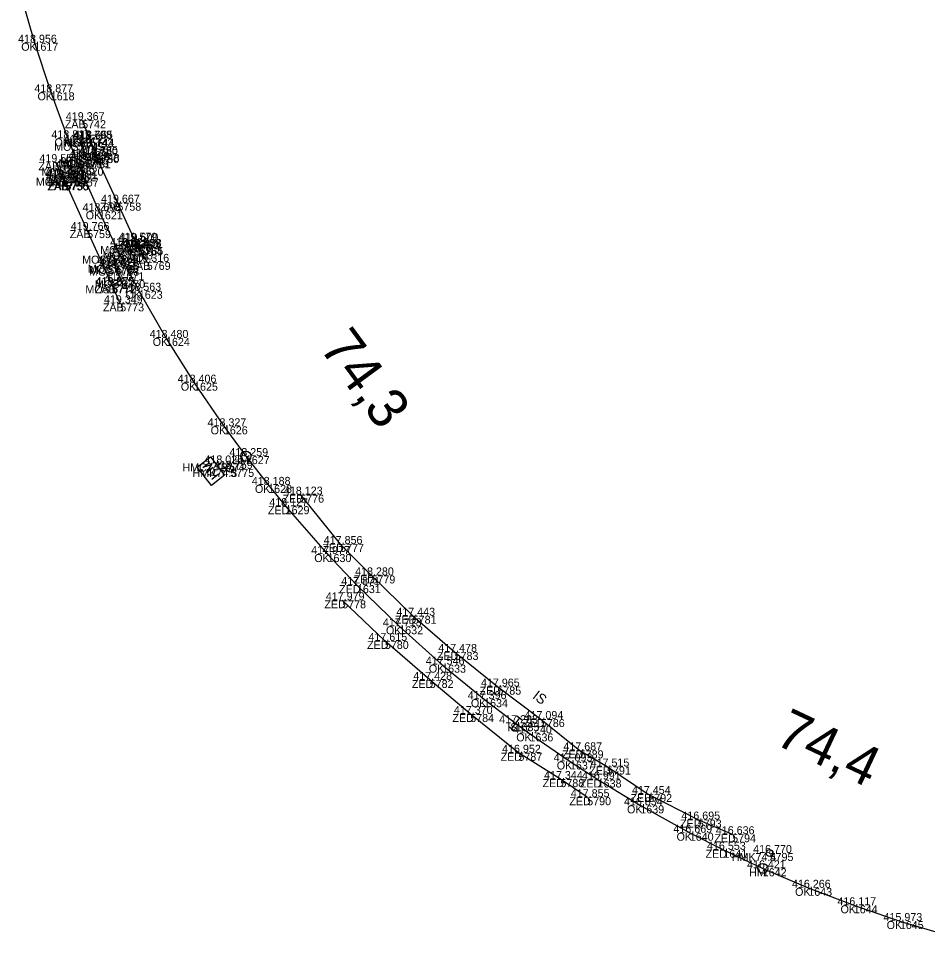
# Model space of a CAD drawing. Extents: x -621782 to -610392, y -1141853 to -1122321.
# Drawn here: x -619452.2 to -619315.9, y -1130073.6 to -1129936.1 of the extents above; entities that cross this region are included whole.
import ezdxf

# ---------------------------------------------------------------- set-up
doc = ezdxf.new("R2010")
doc.units = 0
for name, color, linetype in [('Vrstva 1', 7, 'Continuous'), ('Vrstva 13', 7, 'Continuous'), ('Vrstva 17', 7, 'Continuous'), ('Vrstva 18', 7, 'Continuous'), ('Vrstva 3', 7, 'Continuous'), ('Vrstva 60', 7, 'Continuous'), ('Vrstva 61', 7, 'Continuous'), ('Vrstva 62', 7, 'Continuous'), ('Vrstva 7', 7, 'Continuous')]:
    doc.layers.add(name, color=color, linetype=linetype)

msp = doc.modelspace()

# ---------------------------------------------------------------- linework, layer by layer
at = {"layer": 'Vrstva 1'}
msp.add_lwpolyline([(-619451.85, -1129932.46), (-619449.77, -1129939.77), (-619447.33, -1129947.2), (-619444.78, -1129954.1), (-619443, -1129958.49), (-619440.11, -1129965.04), (-619436.88, -1129971.69), (-619434.13, -1129976.95), (-619430.06, -1129984.02), (-619425.85, -1129990.73), (-619421.38, -1129997.27), (-619418.1, -1130001.74), (-619414.75, -1130006.05), (-619412.13, -1130009.24), (-619405.85, -1130016.42), (-619401.45, -1130021.07), (-619395.11, -1130027.25), (-619388.68, -1130033), (-619382.39, -1130038.17), (-619377.68, -1130041.77), (-619375.59, -1130043.3), (-619369.52, -1130047.51), (-619365.37, -1130050.21), (-619358.98, -1130054.09), (-619351.57, -1130058.19), (-619346.53, -1130060.75), (-619340.64, -1130063.53), (-619333.81, -1130066.45), (-619327, -1130069.07), (-619320.09, -1130071.43), (-619312.85, -1130073.62)], dxfattribs=at)
at = {"layer": 'Vrstva 13'}
for points in [[(-619409.94, -1130007.51), (-619403.96, -1130014.91), (-619399.27, -1130019.62), (-619393.09, -1130025.67), (-619386.81, -1130031.09), (-619380.4, -1130036.29), (-619373.88, -1130041.15), (-619368.06, -1130045.84), (-619363.97, -1130048.27), (-619357.79, -1130052.39), (-619350.37, -1130056.22), (-619345.22, -1130058.42)], [(-619366.94, -1130052.87), (-619370.96, -1130050.15), (-619377.25, -1130046.21), (-619384.47, -1130040.39), (-619390.54, -1130035.28), (-619397.26, -1130029.44), (-619403.66, -1130023.35)]]:
    msp.add_lwpolyline(points, dxfattribs=at)
at = {"layer": 'Vrstva 17'}
for points in [[(-619442.62, -1129951.38), (-619441.51, -1129954.17), (-619440.59, -1129956.43), (-619440.64, -1129956.61), (-619437.34, -1129963.75), (-619434.72, -1129969.46), (-619434.56, -1129969.53), (-619434.15, -1129970.44), (-619432.94, -1129972.62)], [(-619436.91, -1129978.84), (-619438.12, -1129976.11), (-619441.88, -1129967.85), (-619445.13, -1129960.66), (-619445.25, -1129960.71), (-619445.56, -1129959.96), (-619446.58, -1129957.68)]]:
    msp.add_lwpolyline(points, dxfattribs=at)
at = {"layer": 'Vrstva 18'}
for points in [[(-619445.62, -1129960.01), (-619444.09, -1129959.33), (-619443.72, -1129960.12), (-619441.91, -1129957.39), (-619442.22, -1129957.23), (-619441.98, -1129956.86), (-619442.88, -1129954.77), (-619441.38, -1129954.14)], [(-619438.2, -1129976.14), (-619436.76, -1129975.37), (-619437.65, -1129973.49), (-619437.52, -1129973.22), (-619437.82, -1129973.06), (-619435.98, -1129970.24), (-619435.59, -1129971.06), (-619434.05, -1129970.39)]]:
    msp.add_lwpolyline(points, dxfattribs=at)
at = {"layer": 'Vrstva 3'}
for p, q in [((-619377.07, -1130040.98), (-619378.28, -1130042.57)), ((-619377.47, -1130040.68), (-619376.67, -1130041.28)), ((-619378.68, -1130042.26), (-619377.89, -1130042.87))]:
    msp.add_line(p, q, dxfattribs=at)
at = {"layer": 'Vrstva 60'}
for p, q in [((-619449.77, -1129939.77), (-619449.77, -1129939.77)), ((-619447.33, -1129947.2), (-619447.33, -1129947.2)), ((-619442.62, -1129951.38), (-619442.62, -1129951.38)), ((-619444.78, -1129954.1), (-619444.78, -1129954.1)), ((-619442.88, -1129954.77), (-619442.88, -1129954.77)), ((-619441.51, -1129954.17), (-619441.51, -1129954.17)), ((-619441.38, -1129954.14), (-619441.38, -1129954.14)), ((-619442.22, -1129957.23), (-619442.22, -1129957.23)), ((-619441.98, -1129956.86), (-619441.98, -1129956.86)), ((-619441.91, -1129957.39), (-619441.91, -1129957.39)), ((-619440.64, -1129956.61), (-619440.64, -1129956.61)), ((-619440.59, -1129956.43), (-619440.59, -1129956.43)), ((-619446.58, -1129957.68), (-619446.58, -1129957.68)), ((-619443, -1129958.49), (-619443, -1129958.49)), ((-619445.62, -1129960.01), (-619445.62, -1129960.01)), ((-619445.56, -1129959.96), (-619445.56, -1129959.96)), ((-619444.09, -1129959.33), (-619444.09, -1129959.33)), ((-619443.72, -1129960.12), (-619443.72, -1129960.12)), ((-619445.25, -1129960.71), (-619445.25, -1129960.71)), ((-619445.13, -1129960.66), (-619445.13, -1129960.66)), ((-619437.34, -1129963.75), (-619437.34, -1129963.75)), ((-619440.11, -1129965.04), (-619440.11, -1129965.04)), ((-619441.88, -1129967.85), (-619441.88, -1129967.85)), ((-619434.72, -1129969.46), (-619434.72, -1129969.46)), ((-619434.56, -1129969.53), (-619434.56, -1129969.53)), ((-619435.98, -1129970.24), (-619435.98, -1129970.24)), ((-619435.59, -1129971.06), (-619435.59, -1129971.06)), ((-619434.15, -1129970.44), (-619434.15, -1129970.44)), ((-619434.05, -1129970.39), (-619434.05, -1129970.39)), ((-619436.88, -1129971.69), (-619436.88, -1129971.69)), ((-619432.94, -1129972.62), (-619432.94, -1129972.62)), ((-619437.82, -1129973.06), (-619437.82, -1129973.06)), ((-619437.65, -1129973.49), (-619437.65, -1129973.49)), ((-619437.52, -1129973.22), (-619437.52, -1129973.22)), ((-619436.76, -1129975.37), (-619436.76, -1129975.37)), ((-619438.2, -1129976.14), (-619438.2, -1129976.14)), ((-619438.12, -1129976.11), (-619438.12, -1129976.11)), ((-619434.13, -1129976.95), (-619434.13, -1129976.95)), ((-619436.91, -1129978.84), (-619436.91, -1129978.84)), ((-619430.06, -1129984.02), (-619430.06, -1129984.02)), ((-619425.85, -1129990.73), (-619425.85, -1129990.73)), ((-619421.38, -1129997.27), (-619421.38, -1129997.27)), ((-619421.85, -1130002.84), (-619421.85, -1130002.84)), ((-619418.1, -1130001.74), (-619418.1, -1130001.74)), ((-619420.42, -1130003.65), (-619420.42, -1130003.65)), ((-619414.75, -1130006.05), (-619414.75, -1130006.05)), ((-619409.94, -1130007.51), (-619409.94, -1130007.51)), ((-619412.13, -1130009.24), (-619412.13, -1130009.24)), ((-619403.96, -1130014.91), (-619403.96, -1130014.91)), ((-619405.85, -1130016.42), (-619405.85, -1130016.42)), ((-619399.27, -1130019.62), (-619399.27, -1130019.62)), ((-619401.45, -1130021.07), (-619401.45, -1130021.07)), ((-619403.66, -1130023.35), (-619403.66, -1130023.35)), ((-619393.09, -1130025.67), (-619393.09, -1130025.67)), ((-619395.11, -1130027.25), (-619395.11, -1130027.25)), ((-619397.26, -1130029.44), (-619397.26, -1130029.44)), ((-619386.81, -1130031.09), (-619386.81, -1130031.09)), ((-619388.68, -1130033), (-619388.68, -1130033)), ((-619390.54, -1130035.28), (-619390.54, -1130035.28)), ((-619380.4, -1130036.29), (-619380.4, -1130036.29)), ((-619382.39, -1130038.17), (-619382.39, -1130038.17)), ((-619384.47, -1130040.39), (-619384.47, -1130040.39)), ((-619373.88, -1130041.15), (-619373.88, -1130041.15)), ((-619377.68, -1130041.77), (-619377.68, -1130041.77)), ((-619375.59, -1130043.3), (-619375.59, -1130043.3)), ((-619377.25, -1130046.21), (-619377.25, -1130046.21)), ((-619368.06, -1130045.84), (-619368.06, -1130045.84)), ((-619369.52, -1130047.51), (-619369.52, -1130047.51)), ((-619363.97, -1130048.27), (-619363.97, -1130048.27)), ((-619370.96, -1130050.15), (-619370.96, -1130050.15)), ((-619365.37, -1130050.21), (-619365.37, -1130050.21)), ((-619357.79, -1130052.39), (-619357.79, -1130052.39)), ((-619366.94, -1130052.87), (-619366.94, -1130052.87)), ((-619358.98, -1130054.09), (-619358.98, -1130054.09)), ((-619350.37, -1130056.22), (-619350.37, -1130056.22)), ((-619351.57, -1130058.19), (-619351.57, -1130058.19)), ((-619345.22, -1130058.42), (-619345.22, -1130058.42)), ((-619346.53, -1130060.75), (-619346.53, -1130060.75)), ((-619339.61, -1130061.23), (-619339.61, -1130061.23)), ((-619340.64, -1130063.53), (-619340.64, -1130063.53)), ((-619333.81, -1130066.45), (-619333.81, -1130066.45)), ((-619327, -1130069.07), (-619327, -1130069.07)), ((-619320.09, -1130071.43), (-619320.09, -1130071.43))]:
    msp.add_line(p, q, dxfattribs=at)
at = {"layer": 'Vrstva 7'}
for p, q in [((-619421.85, -1130002.84), (-619422.34, -1130003.22)), ((-619422.95, -1130004.61), (-619422.71, -1130003.75)), ((-619420.45, -1130003.61), (-619420.39, -1130003.69)), ((-619423.7, -1130004.51), (-619422.53, -1130004.66)), ((-619423.19, -1130005.17), (-619422.2, -1130004.41)), ((-619339.66, -1130061.21), (-619339.57, -1130061.25))]:
    msp.add_line(p, q, dxfattribs=at)
msp.add_lwpolyline([(-619421.27, -1130004.6), (-619423.23, -1130006.12), (-619425.37, -1130003.37), (-619423.41, -1130001.85)], close=True, dxfattribs=at)
msp.add_lwpolyline([(-619422.97, -1130003.42), (-619423.95, -1130004.19), (-619423.26, -1130003.04), (-619424.54, -1130003.44), (-619423.55, -1130002.67)], dxfattribs=at)
for centre, radius in [((-619418.1, -1130001.74), 0.75), ((-619420.42, -1130003.65), 0.5), ((-619339.61, -1130061.23), 0.5), ((-619340.64, -1130063.53), 0.75)]:
    msp.add_circle(centre, radius, dxfattribs=at)

# ---------------------------------------------------------------- texts
at = {"layer": 'Vrstva 3'}
msp.add_text('IS', height=1.5, rotation=322.591, dxfattribs=at).set_placement((-619375.24, -1130037.94))
at = {"layer": 'Vrstva 60'}
for s, p in [('1617', (-619449.77, -1129940.97)), ('1618', (-619447.33, -1129948.4)), ('5742', (-619442.62, -1129952.58)), ('1619', (-619444.78, -1129955.3)), ('5745', (-619442.88, -1129955.97)), ('5743', (-619441.51, -1129955.37)), ('5744', (-619441.38, -1129955.34)), ('5749', (-619442.22, -1129958.43)), ('5747', (-619441.98, -1129958.06)), ('5751', (-619441.91, -1129958.59)), ('5750', (-619440.64, -1129957.81)), ('5748', (-619440.59, -1129957.63)), ('5746', (-619446.58, -1129958.88)), ('1620', (-619443, -1129959.69)), ('5754', (-619445.62, -1129961.21)), ('5753', (-619445.56, -1129961.16)), ('5752', (-619444.09, -1129960.53)), ('5757', (-619443.72, -1129961.32)), ('5756', (-619445.25, -1129961.91)), ('5755', (-619445.13, -1129961.86)), ('5758', (-619437.34, -1129964.95)), ('1621', (-619440.11, -1129966.24)), ('5759', (-619441.88, -1129969.05)), ('5760', (-619434.72, -1129970.66)), ('5762', (-619434.56, -1129970.73)), ('5761', (-619435.98, -1129971.44)), ('5763', (-619435.59, -1129972.26)), ('5764', (-619434.15, -1129971.64)), ('5765', (-619434.05, -1129971.59)), ('1622', (-619436.88, -1129972.89)), ('5769', (-619432.94, -1129973.82)), ('5766', (-619437.82, -1129974.26)), ('5768', (-619437.65, -1129974.69)), ('5767', (-619437.52, -1129974.42)), ('5770', (-619436.76, -1129976.57)), ('5771', (-619438.2, -1129977.34)), ('5772', (-619438.12, -1129977.31)), ('1623', (-619434.13, -1129978.15)), ('5773', (-619436.91, -1129980.04)), ('1624', (-619430.06, -1129985.22)), ('1625', (-619425.85, -1129991.93)), ('1626', (-619421.38, -1129998.47)), ('5774', (-619421.85, -1130004.04)), ('1627', (-619418.1, -1130002.94)), ('5775', (-619420.42, -1130004.85)), ('1628', (-619414.75, -1130007.25)), ('5776', (-619409.94, -1130008.71)), ('1629', (-619412.13, -1130010.44)), ('5777', (-619403.96, -1130016.1)), ('1630', (-619405.85, -1130017.62)), ('5779', (-619399.27, -1130020.82)), ('1631', (-619401.45, -1130022.27)), ('5778', (-619403.66, -1130024.55)), ('5781', (-619393.09, -1130026.86)), ('1632', (-619395.11, -1130028.45)), ('5780', (-619397.26, -1130030.64)), ('5783', (-619386.81, -1130032.29)), ('1633', (-619388.68, -1130034.2)), ('5782', (-619390.54, -1130036.49)), ('5785', (-619380.4, -1130037.49)), ('1634', (-619382.39, -1130039.37)), ('5784', (-619384.47, -1130041.59)), ('5786', (-619373.88, -1130042.35)), ('1635', (-619377.68, -1130042.97)), ('1636', (-619375.59, -1130044.5)), ('5787', (-619377.25, -1130047.41)), ('5789', (-619368.06, -1130047.04)), ('1637', (-619369.52, -1130048.71)), ('5791', (-619363.97, -1130049.47)), ('5788', (-619370.96, -1130051.35)), ('1638', (-619365.37, -1130051.41)), ('5792', (-619357.79, -1130053.58)), ('5790', (-619366.94, -1130054.07)), ('1639', (-619358.98, -1130055.29)), ('5793', (-619350.37, -1130057.42)), ('1640', (-619351.57, -1130059.39)), ('5794', (-619345.22, -1130059.62)), ('1641', (-619346.53, -1130061.95)), ('5795', (-619339.61, -1130062.43)), ('1642', (-619340.64, -1130064.73)), ('1643', (-619333.81, -1130067.65)), ('1644', (-619327, -1130070.27)), ('1645', (-619320.09, -1130072.63))]:
    msp.add_text(s, height=1.2, dxfattribs=at).set_placement(p)
at = {"layer": 'Vrstva 61'}
for s, p in [('418.956', (-619452.22, -1129939.77)), ('418.877', (-619449.78, -1129947.2)), ('419.367', (-619445.07, -1129951.38)), ('418.817', (-619447.23, -1129954.1)), ('419.798', (-619443.97, -1129954.17)), ('418.665', (-619443.84, -1129954.14)), ('418.672', (-619445.33, -1129954.77)), ('418.689', (-619444.67, -1129957.23)), ('418.679', (-619444.44, -1129956.86)), ('418.688', (-619444.37, -1129957.39)), ('419.780', (-619443.09, -1129956.61)), ('419.785', (-619443.05, -1129956.43)), ('419.557', (-619449.03, -1129957.68)), ('418.775', (-619445.46, -1129958.49)), ('418.769', (-619448.07, -1129960.01)), ('419.882', (-619448, -1129959.96)), ('418.786', (-619446.55, -1129959.33)), ('418.781', (-619446.08, -1129960.12)), ('419.898', (-619447.71, -1129960.71)), ('419.901', (-619447.49, -1129960.66)), ('419.667', (-619439.79, -1129963.75)), ('418.698', (-619442.56, -1129965.04)), ('419.766', (-619444.33, -1129967.85)), ('419.579', (-619437.17, -1129969.46)), ('419.600', (-619437.01, -1129969.53)), ('418.528', (-619438.43, -1129970.24)), ('418.518', (-619438.04, -1129971.06)), ('419.579', (-619436.61, -1129970.44)), ('418.458', (-619436.51, -1129970.39)), ('418.616', (-619439.34, -1129971.69)), ('418.634', (-619440.27, -1129973.06)), ('418.617', (-619440.1, -1129973.49)), ('418.629', (-619439.97, -1129973.22)), ('419.316', (-619435.39, -1129972.62)), ('418.555', (-619440.65, -1129976.14)), ('419.675', (-619440.58, -1129976.11)), ('418.571', (-619439.12, -1129975.37)), ('418.563', (-619436.58, -1129976.95)), ('419.349', (-619439.36, -1129978.84)), ('418.480', (-619432.51, -1129984.02)), ('418.406', (-619428.31, -1129990.73)), ('418.327', (-619423.83, -1129997.27)), ('418.025', (-619424.3, -1130002.84)), ('418.259', (-619420.56, -1130001.74)), ('418.759', (-619422.87, -1130003.65)), ('418.188', (-619417.2, -1130006.05)), ('418.123', (-619412.39, -1130007.51)), ('418.127', (-619414.58, -1130009.24)), ('417.856', (-619406.42, -1130014.91)), ('417.977', (-619408.3, -1130016.42)), ('418.280', (-619401.72, -1130019.62)), ('417.871', (-619403.8, -1130021.07)), ('417.979', (-619406.11, -1130023.35)), ('417.443', (-619395.54, -1130025.67)), ('417.713', (-619397.56, -1130027.25)), ('417.615', (-619399.72, -1130029.44)), ('417.478', (-619389.26, -1130031.09)), ('417.546', (-619391.13, -1130033)), ('417.428', (-619393, -1130035.28)), ('417.965', (-619382.86, -1130036.29)), ('417.396', (-619384.84, -1130038.17)), ('417.370', (-619386.92, -1130040.39)), ('417.094', (-619376.33, -1130041.15)), ('417.283', (-619380.13, -1130041.77)), ('417.240', (-619378.04, -1130043.3)), ('416.952', (-619379.7, -1130046.21)), ('417.687', (-619370.51, -1130045.84)), ('417.093', (-619371.97, -1130047.51)), ('417.515', (-619366.43, -1130048.27)), ('417.344', (-619373.41, -1130050.15)), ('416.991', (-619367.73, -1130050.21)), ('417.855', (-619369.4, -1130052.87)), ('417.454', (-619360.24, -1130052.39)), ('416.834', (-619361.43, -1130054.09)), ('416.695', (-619352.83, -1130056.22)), ('416.669', (-619354.02, -1130058.19)), ('416.636', (-619347.67, -1130058.42)), ('416.553', (-619348.99, -1130060.75)), ('416.770', (-619342.07, -1130061.23)), ('416.421', (-619342.99, -1130063.53)), ('416.266', (-619336.26, -1130066.45)), ('416.117', (-619329.45, -1130069.07)), ('415.973', (-619322.54, -1130071.43))]:
    msp.add_text(s, height=1.2, dxfattribs=at).set_placement(p)
at = {"layer": 'Vrstva 62'}
for s, p in [('OK', (-619451.75, -1129940.97)), ('OK', (-619449.31, -1129948.4)), ('ZAB', (-619445.22, -1129952.58)), ('OK', (-619446.77, -1129955.3)), ('MOST', (-619446.82, -1129955.97)), ('MOST', (-619445.33, -1129955.34)), ('ZAB', (-619444.11, -1129955.37)), ('MOST', (-619446.16, -1129958.43)), ('MOST', (-619445.93, -1129958.06)), ('MOST', (-619445.86, -1129958.59)), ('ZAB', (-619443.24, -1129957.81)), ('ZAB', (-619443.19, -1129957.63)), ('ZAB', (-619449.18, -1129958.88)), ('MOSTBS', (-619448.73, -1129959.69)), ('MOST', (-619449.56, -1129961.21)), ('ZAB', (-619448.16, -1129961.16)), ('MOST', (-619448.04, -1129960.53)), ('MOST', (-619447.67, -1129961.32)), ('ZAB', (-619447.85, -1129961.91)), ('ZAB', (-619447.74, -1129961.86)), ('ZAB', (-619439.94, -1129964.95)), ('OK', (-619442.09, -1129966.24)), ('ZAB', (-619444.48, -1129969.05)), ('ZAB', (-619437.32, -1129970.66)), ('ZAB', (-619437.16, -1129970.73)), ('MOST', (-619439.92, -1129971.44)), ('MOST', (-619439.53, -1129972.26)), ('MOST', (-619438, -1129971.59)), ('ZAB', (-619436.75, -1129971.64)), ('MOSTBS', (-619442.62, -1129972.89)), ('ZAB', (-619435.54, -1129973.82)), ('MOST', (-619441.77, -1129974.26)), ('MOST', (-619441.59, -1129974.69)), ('MOST', (-619441.46, -1129974.42)), ('MOST', (-619440.71, -1129976.57)), ('MOST', (-619442.14, -1129977.34)), ('ZAB', (-619440.72, -1129977.31)), ('OK', (-619436.11, -1129978.15)), ('ZAB', (-619439.51, -1129980.04)), ('OK', (-619432.05, -1129985.22)), ('OK', (-619427.84, -1129991.93)), ('OK', (-619423.37, -1129998.47)), ('HMC74.3', (-619427.59, -1130004.04)), ('HM', (-619420.14, -1130002.94)), ('HMK74.3', (-619426.08, -1130004.85)), ('OK', (-619416.73, -1130007.25)), ('ZED', (-619412.61, -1130008.71)), ('ZED', (-619414.8, -1130010.44)), ('ZED', (-619406.64, -1130016.1)), ('OK', (-619407.84, -1130017.62)), ('ZED', (-619401.95, -1130020.82)), ('ZED', (-619404.12, -1130022.27)), ('ZED', (-619406.33, -1130024.55)), ('ZED', (-619395.76, -1130026.86)), ('OK', (-619397.1, -1130028.45)), ('ZED', (-619399.93, -1130030.64)), ('ZED', (-619389.48, -1130032.29)), ('OK', (-619390.67, -1130034.2)), ('ZED', (-619393.22, -1130036.49)), ('ZED', (-619383.07, -1130037.49)), ('OK', (-619384.37, -1130039.37)), ('ZED', (-619387.14, -1130041.59)), ('ZED', (-619376.55, -1130042.35)), ('IS', (-619378.91, -1130042.97)), ('OK', (-619377.57, -1130044.5)), ('ZED', (-619379.92, -1130047.41)), ('ZED', (-619370.73, -1130047.04)), ('OK', (-619371.5, -1130048.71)), ('ZED', (-619366.64, -1130049.47)), ('ZED', (-619373.63, -1130051.35)), ('ZED', (-619368.04, -1130051.41)), ('ZED', (-619360.46, -1130053.58)), ('ZED', (-619369.62, -1130054.07)), ('OK', (-619360.97, -1130055.29)), ('ZED', (-619353.04, -1130057.42)), ('OK', (-619353.55, -1130059.39)), ('ZED', (-619347.89, -1130059.62)), ('ZED', (-619349.21, -1130061.95)), ('HMK74.4', (-619345.28, -1130062.43)), ('HM', (-619342.67, -1130064.73)), ('OK', (-619335.79, -1130067.65)), ('OK', (-619328.98, -1130070.27)), ('OK', (-619322.07, -1130072.63))]:
    msp.add_text(s, height=1.2, dxfattribs=at).set_placement(p)
at = {"layer": 'Vrstva 7'}
for s, rotation, p in [('74,3', 306.2928, (-619407.19, -1129985.48)), ('74,4', 334.7554, (-619339.06, -1130044.81))]:
    msp.add_text(s, height=6, rotation=rotation, dxfattribs=at).set_placement(p)

doc.saveas('drawing.dxf')
